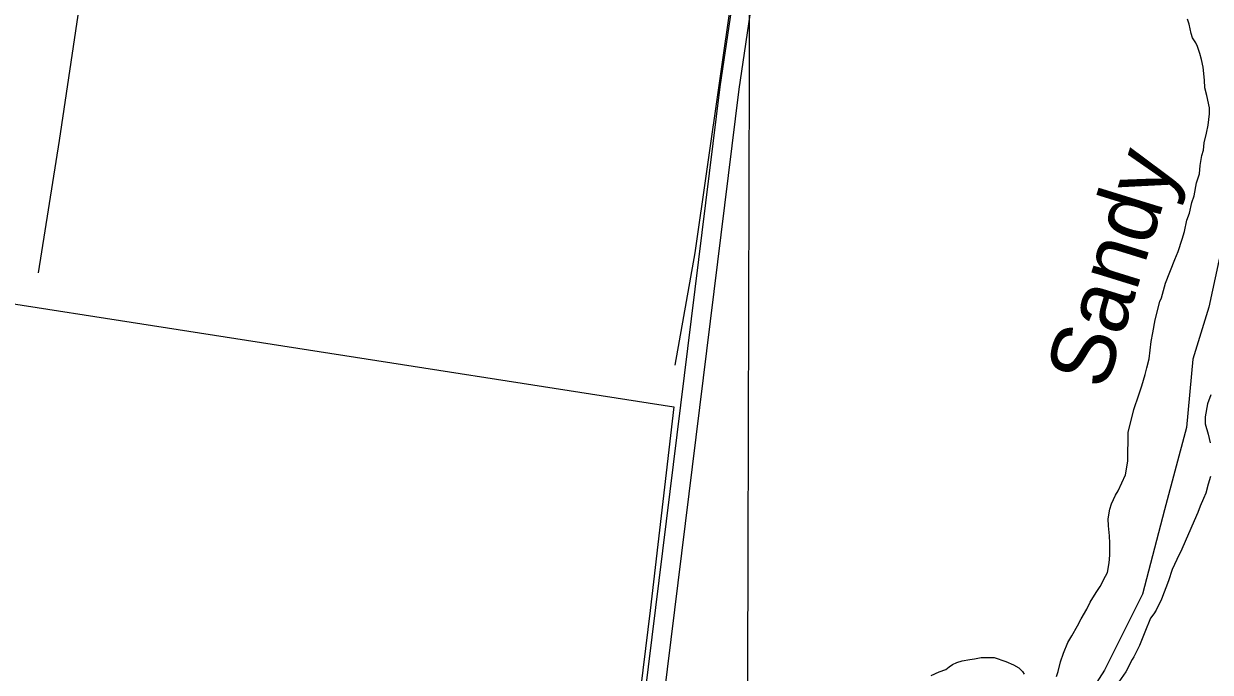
# Model space of a CAD drawing. Extents: x 3161514 to 3199414, y 831166 to 856601.
# Drawn here: x 3169818 to 3171686, y 843838 to 844859 of the extents above; entities that cross this region are included whole.
import ezdxf

# ---------------------------------------------------------------- set-up
doc = ezdxf.new("R2010")
doc.units = 0
for name, color, linetype in [('V-GRID-MAJR', 7, 'Continuous'), ('V-RIVR-IDEN', 7, 'Continuous'), ('V-ROAD-CNTR', 7, 'Continuous'), ('V-SITE-VEGE', 7, 'Continuous'), ('V-TOPO-SHOR', 7, 'Continuous')]:
    doc.layers.add(name, color=color, linetype=linetype)

msp = doc.modelspace()

# ---------------------------------------------------------------- linework, layer by layer
at = {"layer": 'V-GRID-MAJR'}
msp.add_spline([(3170936, 836618.4), (3170954.6, 842678.9), (3170973.1, 848741.2), (3170991.6, 854803.7), (3170991.6, 854805.6)], degree=3, dxfattribs=at)
at = {"layer": 'V-ROAD-CNTR'}
for points in [[(3170729.2, 843056.9), (3170814.5, 843707.1), (3170943.9, 844755.7), (3171195.8, 846454.1), (3171299.1, 847255.9), (3171351.4, 847638.1), (3171399.9, 848031.4), (3171421.5, 848196.3), (3171427.4, 848252.3), (3171427.3, 848291.4), (3171417.9, 848330.6)], [(3170699.4, 843060.8), (3170784.7, 843710.9), (3170914.1, 844759.7), (3171166.1, 846458.2), (3171269.4, 847259.8), (3171321.6, 847642), (3171370.2, 848035.1), (3171391.7, 848199.8), (3171397.4, 848253.8), (3171397.3, 848287.9), (3171388.7, 848323.6)]]:
    msp.add_lwpolyline(points, dxfattribs=at)
at = {"layer": 'V-SITE-VEGE'}
for points in [[(3171595.5, 844372.4), (3171599.2, 844392.8), (3171606.4, 844421.6), (3171609.1, 844427.6), (3171615.4, 844450.5), (3171630.4, 844487.8), (3171635.7, 844500.5), (3171641.9, 844520), (3171645.5, 844531.9), (3171649.1, 844549.7), (3171653.5, 844560.7), (3171657.2, 844577.7), (3171660.7, 844587.9), (3171664.4, 844608.3), (3171668.9, 844622.7), (3171669.9, 844635.5), (3171672.7, 844651.6), (3171675.3, 844660.1), (3171676.3, 844671.2), (3171680, 844686.5), (3171682.7, 844699.2), (3171684.7, 844717.1), (3171684.8, 844726.5), (3171680.8, 844746.1), (3171677.5, 844758.1), (3171676.9, 844770), (3171674.6, 844790.5), (3171672.2, 844802.5), (3171669.8, 844811.9), (3171665.7, 844823), (3171663.2, 844829), (3171658.2, 844836.7), (3171655.7, 844843.6), (3171652.5, 844858.1), (3171650.1, 844865.8)], [(3171444.1, 843831.6), (3171446.7, 843839.3), (3171450.4, 843854.6), (3171454.8, 843868.1), (3171461.9, 843885.1), (3171468, 843895.2), (3171476.7, 843911.3), (3171482.8, 843922.3), (3171491.6, 843937.5), (3171496.8, 843948.5), (3171506.4, 843963.7), (3171512.5, 843973), (3171521.2, 843989.1), (3171523.9, 843995), (3171526.6, 844010.3), (3171527.7, 844022.2), (3171527.9, 844041), (3171527.2, 844052.9), (3171525.7, 844068.3), (3171525, 844079.3), (3171527.8, 844094.6), (3171530.5, 844103.1), (3171536.6, 844116.7), (3171541, 844123.4), (3171552.4, 844148.8), (3171556.1, 844170.1), (3171556.7, 844216.1), (3171562.1, 844236.5), (3171565.8, 844251.8), (3171573.7, 844274.7), (3171578.2, 844289.1), (3171583.6, 844306.9), (3171586.3, 844317.1), (3171589.9, 844331.5), (3171592.8, 844358.8), (3171595.5, 844372.4)], [(3171687.1, 844274.8), (3171681.8, 844260.4), (3171678.1, 844240), (3171677.9, 844228.9), (3171682.8, 844212.7), (3171686, 844199)], [(3171686.2, 844146.1), (3171682.6, 844134.3), (3171679, 844119.8), (3171675.4, 844111.4), (3171670.2, 844099.5), (3171666.6, 844089.3), (3171660.5, 844076.6), (3171641.1, 844031.7), (3171633.2, 844015.7), (3171626.2, 843999.6), (3171620, 843981.8), (3171609.4, 843952.9), (3171600.6, 843936), (3171597.1, 843930.1), (3171591.9, 843923.3), (3171583.1, 843901.3), (3171574.3, 843880.1), (3171565.5, 843862.4), (3171562.9, 843858.1), (3171553.2, 843838.7), (3171538.5, 843817.6)], [(3171246.4, 843832.7), (3171259.3, 843838.5), (3171269.5, 843842.6), (3171274.7, 843846.8), (3171279.9, 843850.1), (3171286.7, 843853.4), (3171295.3, 843855.9), (3171307.3, 843858.2), (3171314.9, 843859), (3171325.2, 843861.4), (3171345.6, 843861.1), (3171364.3, 843854.9), (3171376.2, 843849.6), (3171384.6, 843845.2), (3171390.5, 843839.2), (3171393, 843834.9)]]:
    msp.add_lwpolyline(points, dxfattribs=at)
at = {"layer": 'V-TOPO-SHOR'}
for points in [[(3171209, 848216.8), (3171349.6, 848264.2), (3171395.4, 848281.6), (3171376.4, 848130), (3171318, 847678.4), (3171245.4, 847121), (3171196.4, 846724.7), (3171180.6, 846598.4), (3171108, 846086.8), (3171027.5, 845557.9), (3170951.7, 845036.8), (3170874.3, 844498.4), (3170842.7, 844321.5)], [(3170271.1, 847294.7), (3170192.2, 846805.2), (3170113.2, 846301.5), (3170034.3, 845760), (3169952.2, 845204.2), (3169873.2, 844675.2), (3169840.1, 844466.8)], [(3171828.8, 844864.3), (3171759.3, 844687.5), (3171699.3, 844485.4), (3171683.5, 844412.7), (3171658.3, 844330.6), (3171648.8, 844223.2), (3171614.1, 844093.8), (3171579.3, 843961.1), (3171519.3, 843841.1), (3171462.5, 843752.7), (3171443.5, 843686.4), (3171459.3, 843635.9), (3171487.7, 843503.2), (3171541.4, 843329.6), (3171591.9, 843222.2), (3171604.6, 843184.3)], [(3167881, 844722.1), (3168537.2, 844618.5), (3169575.7, 844453.2), (3170841.1, 844255.9), (3170804.1, 843935.2), (3170747.4, 843473.9), (3170661, 842788.2), (3170614.2, 842450.2)]]:
    msp.add_lwpolyline(points, dxfattribs=at)

# ---------------------------------------------------------------- texts
at = {"layer": 'V-RIVR-IDEN'}
msp.add_text('Sandy', height=100, rotation=72.7839, dxfattribs=at).set_placement((3171521, 844279.9))

doc.saveas('drawing.dxf')
